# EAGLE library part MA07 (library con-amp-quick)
AMP QUICK CONNECTOR
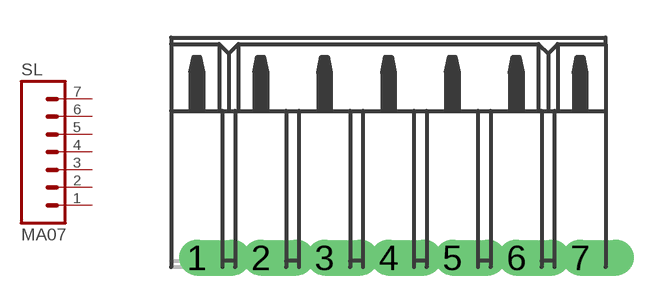
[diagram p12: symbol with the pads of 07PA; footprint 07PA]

Designator prefix SL

## MA07  [07PA]
1  1  pas
2  2  pas
3  3  pas
4  4  pas
5  5  pas
6  6  pas
7  7  pas

## Footprint 07PA (pad centres in mm)
AMP QUICK CONNECTOR
drill 0.914 offset: 1 -7.62,0; 2 -5.08,0; 3 -2.54,0; 4 0,0; 5 2.54,0; 6 5.08,0; 7 7.62,0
